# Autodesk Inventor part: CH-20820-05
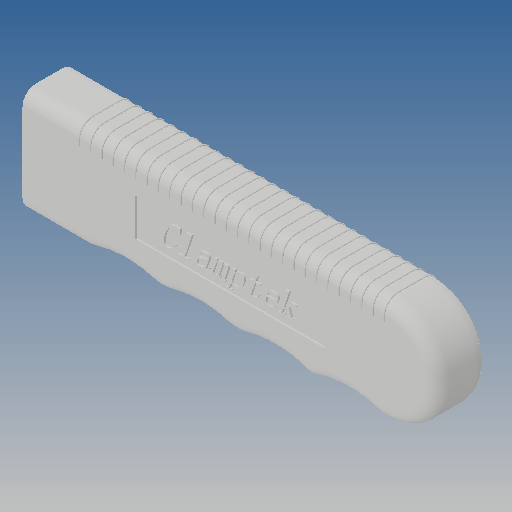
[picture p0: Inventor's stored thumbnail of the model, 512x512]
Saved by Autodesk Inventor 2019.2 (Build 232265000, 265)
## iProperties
Created: 2011-12
Part Number: CH-20820-05
Material: Ogólny
Document SubType Name: Modeling
Designer: CADENGINEERING4
Density: 1 g/cm^3
Appearance: Domyślna
Author: CADENGINEERING4
Revision Number: ÈÎºÎ
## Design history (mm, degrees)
feature "Ô²½Ç12"
node "Bryła1"
